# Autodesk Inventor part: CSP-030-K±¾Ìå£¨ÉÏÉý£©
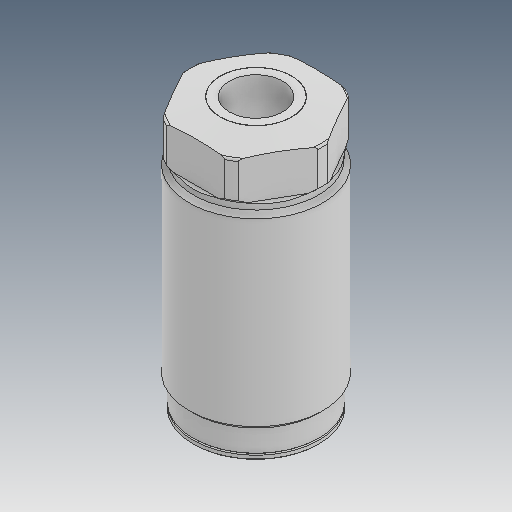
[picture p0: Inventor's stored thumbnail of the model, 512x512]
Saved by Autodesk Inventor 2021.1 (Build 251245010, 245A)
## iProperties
Created: 2019-01
Part Number: CSP-030-K±¾Ìå£¨ÉÏÉý£©
Material: Ogólny
Document SubType Name: Modeling
Designer: user
Density: 1 g/cm^3
Appearance: Domyślna
Author: user
Revision Number: ÈÎºÎ
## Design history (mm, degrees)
feature "Ô²½Ç2"
node "Bryła1"
